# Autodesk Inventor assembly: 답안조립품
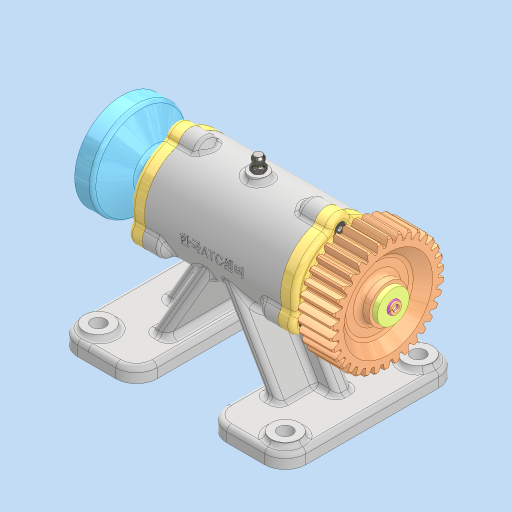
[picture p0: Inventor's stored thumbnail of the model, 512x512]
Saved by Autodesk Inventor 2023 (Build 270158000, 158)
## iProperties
Created: 2026-04
Part Number: 답안조립품
Document SubType Name: Assembly
Designer: home
Author: home
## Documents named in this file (16)
- C:\Users\home\Desktop\760403V1009\답안조립품.iam
- C:\Users\home\Desktop\760403V1009\본체.ipt
- C:\Users\home\Desktop\760403V1009\6각 구멍붙이 볼트 M4x12.ipt
- C:\Users\home\Desktop\760403V1009\그리스 니플 M6x0,75.ipt
- C:\Users\home\Desktop\760403V1009\깊은 홈 볼 베어링 6004.ipt
- C:\Users\home\Desktop\760403V1009\스퍼 기어.ipt
- C:\Users\home\Desktop\760403V1009\스프링 와셔 M4.ipt
- C:\Users\home\Desktop\760403V1009\실링.ipt
- C:\Users\home\Desktop\760403V1009\엔드 캡.ipt
- C:\Users\home\Desktop\760403V1009\오일 실 20 35 8.ipt
- C:\Users\home\Desktop\760403V1009\축.ipt
- C:\Users\home\Desktop\760403V1009\커버.ipt
- C:\Users\home\Desktop\760403V1009\평 와셔 M4.ipt
- C:\Users\home\Desktop\760403V1009\평행 키 4x4x14.ipt
- C:\Users\home\Desktop\760403V1009\플랜지.ipt
- C:\Users\home\Desktop\760403V1009\플러그 M6x0,75.ipt
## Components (9 placed, 4 different names)
1. 6각 구멍붙이 볼트 M4x12:1
2. 그리스 니플 M6x0,75:1
3. 플랜지:1
4. 플러그 M6x0,75:1
5. 6각 구멍붙이 볼트 M4x12:2
6. 6각 구멍붙이 볼트 M4x12:3
7. 6각 구멍붙이 볼트 M4x12:4
8. 6각 구멍붙이 볼트 M4x12:5
9. 6각 구멍붙이 볼트 M4x12:6
